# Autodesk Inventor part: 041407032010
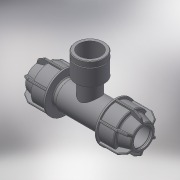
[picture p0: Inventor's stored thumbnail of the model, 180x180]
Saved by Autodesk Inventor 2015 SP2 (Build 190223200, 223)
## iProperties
Created: 2017-08
Part Number: 041407032010
Material: Generic
Description: PLASSON IRRIFIT TEE FEMALE ADAPTOR 32-1"-32
Document SubType Name: Modeling
Designer: KIM
Density: 1 g/cm^3
Appearance: Default
Author: KIM
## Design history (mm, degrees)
derived "041407.ipt"
feature "Solid1::041407.ipt"
feature "Solid2::041407.ipt"
tag "TaggingFeature1"
body "Solid1"
other parameters: "d1" = 32, "d2" = 38, "d4" = 15 deg, "d5" = 36.1, "d6" = 14.44, "d10" = 57, "d16" = 32.64, "d17" = 1.9, "d22" = 41.6, "d24" = 1.9, "d25" = 51.3, "d26" = 42.75, "d27" = 1.9, "d28" = 135 deg, "d29" = 1.14, "d31" = 1.6, "d46" = 150 deg, "d49" = 2.85, "d50" = 0, "d58" = 0.96, "d61" = 360 deg, "d63" = 28.8, "d64" = 64.5, "d80" = 45.76, "d81" = 0.32, "d94" = 58, "d96" = 31.3521, "d108" = 0.96, "d113" = 16.8819, "d115" = 22.8, "d117" = 21.7053, "d118" = 3.8, "d119" = 19, "d120" = 24.117, "d121" = 0.48234, "d122" = 5.7, "d123" = 3.8, "d128" = 31.3521, "d130" = 0, "d132" = 0, "d_" = 32, "G_" = 24.117, "E_" = 57, "H_" = 129, "l_" = 38, "l_1" = 19, "A_" = 58
